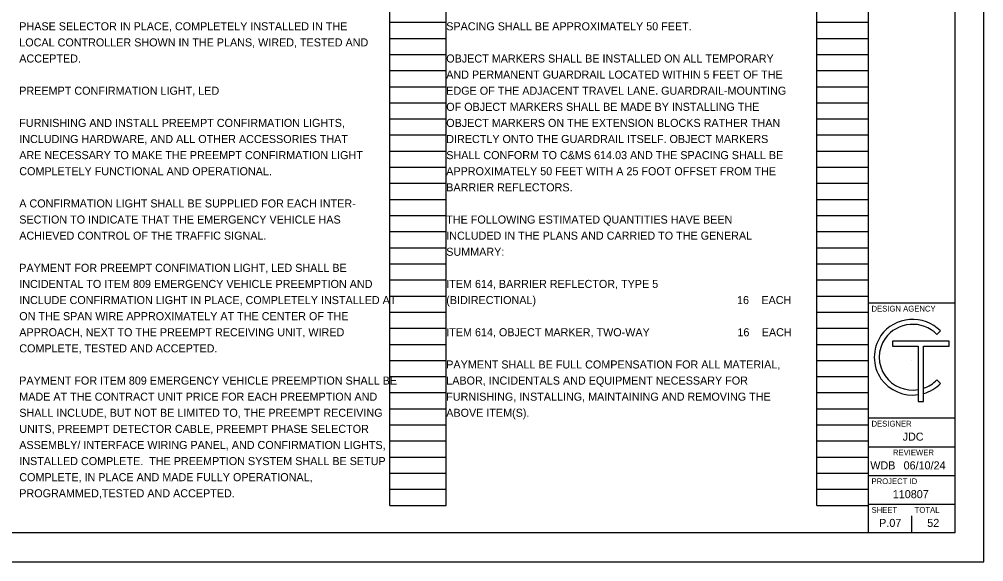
# Model space of a CAD drawing. Extents: x 0 to 34, y 0 to 22.
# Drawn here: x 17.24 to 34, y 0 to 9.43 of the extents above; entities that cross this region are included whole.
import ezdxf

# ---------------------------------------------------------------- set-up
doc = ezdxf.new("R2010")
doc.units = 0
for name, color, linetype in [('SH_Border', 7, 'Continuous'), ('SH_Cut_Line', 7, 'Continuous'), ('SH_Data', 7, 'Continuous'), ('SH_Text', 7, 'Continuous')]:
    doc.layers.add(name, color=color, linetype=linetype)

msp = doc.modelspace()

# ---------------------------------------------------------------- linework, layer by layer
at = {"layer": 'SH_Border'}
for p, q in [((32, 0.5), (32, 21.5)), ((32, 4.5), (33.5, 4.5)), ((32, 2.5), (33.5, 2.5)), ((32, 2), (33.5, 2)), ((32, 1.5), (33.5, 1.5)), ((32, 1), (33.5, 1))]:
    msp.add_line(p, q, dxfattribs=at)
msp.add_lwpolyline([(1.5, 21.5), (33.5, 21.5), (33.5, 0.5), (1.5, 0.5)], close=True, dxfattribs=at)
at = {"layer": 'SH_Cut_Line'}
msp.add_lwpolyline([(0, 0), (34, 0), (34, 22), (0, 22)], close=True, dxfattribs=at)
at = {"layer": 'SH_Data'}
for p, q in [((23.68, 0.98), (23.68, 21.14)), ((24.66, 0.98), (24.66, 21.14)), ((31.1, 0.98), (31.1, 21.14)), ((32, 0.98), (32, 21.14)), ((23.68, 9.38), (24.66, 9.38)), ((31.1, 9.38), (32, 9.38)), ((23.68, 9.1), (24.66, 9.1)), ((31.1, 9.1), (32, 9.1)), ((23.68, 8.82), (24.66, 8.82)), ((31.1, 8.82), (32, 8.82)), ((23.68, 8.54), (24.66, 8.54)), ((31.1, 8.54), (32, 8.54)), ((23.68, 8.26), (24.66, 8.26)), ((31.1, 8.26), (32, 8.26)), ((23.68, 7.98), (24.66, 7.98)), ((31.1, 7.98), (32, 7.98)), ((23.68, 7.7), (24.66, 7.7)), ((31.1, 7.7), (32, 7.7)), ((23.68, 7.42), (24.66, 7.42)), ((31.1, 7.42), (32, 7.42)), ((23.68, 7.14), (24.66, 7.14)), ((31.1, 7.14), (32, 7.14)), ((23.68, 6.86), (24.66, 6.86)), ((31.1, 6.86), (32, 6.86)), ((23.68, 6.58), (24.66, 6.58)), ((31.1, 6.58), (32, 6.58)), ((23.68, 6.3), (24.66, 6.3)), ((31.1, 6.3), (32, 6.3)), ((23.68, 6.02), (24.66, 6.02)), ((31.1, 6.02), (32, 6.02)), ((23.68, 5.74), (24.66, 5.74)), ((31.1, 5.74), (32, 5.74)), ((23.68, 5.46), (24.66, 5.46)), ((31.1, 5.46), (32, 5.46)), ((23.68, 5.18), (24.66, 5.18)), ((31.1, 5.18), (32, 5.18)), ((23.68, 4.9), (24.66, 4.9)), ((31.1, 4.9), (32, 4.9)), ((23.68, 4.62), (24.66, 4.62)), ((31.1, 4.62), (32, 4.62)), ((23.68, 4.34), (24.66, 4.34)), ((31.1, 4.34), (32, 4.34)), ((23.68, 4.06), (24.66, 4.06)), ((31.1, 4.06), (32, 4.06)), ((23.68, 3.78), (24.66, 3.78)), ((31.1, 3.78), (32, 3.78)), ((23.68, 3.5), (24.66, 3.5)), ((31.1, 3.5), (32, 3.5)), ((32.75, 3.5), (32.75, 3.5)), ((23.68, 3.22), (24.66, 3.22)), ((31.1, 3.22), (32, 3.22)), ((23.68, 2.94), (24.66, 2.94)), ((31.1, 2.94), (32, 2.94)), ((23.68, 2.66), (24.66, 2.66)), ((31.1, 2.66), (32, 2.66)), ((23.68, 2.38), (24.66, 2.38)), ((31.1, 2.38), (32, 2.38)), ((23.68, 2.1), (24.66, 2.1)), ((31.1, 2.1), (32, 2.1)), ((23.68, 1.82), (24.66, 1.82)), ((31.1, 1.82), (32, 1.82)), ((23.68, 1.54), (24.66, 1.54)), ((31.1, 1.54), (32, 1.54)), ((23.68, 1.26), (24.66, 1.26)), ((31.1, 1.26), (32, 1.26)), ((23.68, 0.98), (24.66, 0.98)), ((31.1, 0.98), (32, 0.98)), ((32.375, 0.675), (32.375, 0.675)), ((32.75, 0.5), (32.75, 0.8))]:
    msp.add_line(p, q, dxfattribs=at)
at = {"layer": 'SH_Text'}
for p, q in [((33.249, 4.013), (33.187, 3.952)), ((33.249, 4.013), (33.187, 3.952)), ((33.402, 3.833), (32.414, 3.833)), ((32.414, 3.833), (32.414, 3.751)), ((32.414, 3.751), (32.863, 3.751)), ((32.863, 3.751), (32.863, 2.785)), ((32.956, 2.785), (32.956, 3.751)), ((32.956, 3.751), (33.402, 3.751)), ((33.402, 3.751), (33.402, 3.833)), ((33.187, 3.16), (33.249, 3.099)), ((33.187, 3.16), (33.249, 3.099)), ((32.863, 2.993), (32.863, 2.905)), ((32.863, 2.993), (32.863, 2.905)), ((32.956, 2.925), (32.956, 3.016)), ((32.956, 2.925), (32.956, 3.016)), ((32.863, 2.785), (32.956, 2.785))]:
    msp.add_line(p, q, dxfattribs=at)
msp.add_lwpolyline([(32.863, 3.751), (32.863, 2.785), (32.956, 2.785), (32.956, 3.751), (33.402, 3.751), (33.402, 3.833), (32.414, 3.833), (32.414, 3.751)], close=True, dxfattribs=at)
for centre, radius, start, end in [((32.766, 3.535), 0.68, 44.7027, 144.3276), ((32.766, 3.535), 0.68, 44.7027, 144.3276), ((32.766, 3.535), 0.593, 44.7362, 144.1102), ((32.766, 3.535), 0.593, 44.7362, 144.1102), ((32.764, 3.556), 0.666, 145.7329, 214.2671), ((32.764, 3.556), 0.666, 145.7329, 214.2671), ((32.764, 3.556), 0.579, 145.7266, 214.2734), ((32.764, 3.556), 0.579, 145.7266, 214.2734), ((32.766, 3.578), 0.593, 215.8898, 279.4882), ((32.766, 3.578), 0.593, 215.8898, 279.4882), ((32.766, 3.578), 0.68, 215.6724, 278.2613), ((32.766, 3.578), 0.68, 215.6724, 278.2613), ((32.766, 3.578), 0.593, 288.6992, 315.2638), ((32.766, 3.578), 0.593, 288.6992, 315.2638), ((32.766, 3.578), 0.68, 286.2291, 315.2973), ((32.766, 3.578), 0.68, 286.2291, 315.2973)]:
    msp.add_arc(centre, radius, start, end, dxfattribs=at)

# ---------------------------------------------------------------- texts
at = {"layer": 'SH_Data'}
for s, height, p in [('DESIGN AGENCY', 0.1, (32.05, 4.35)), ('DESIGNER', 0.1, (32.05, 2.35)), ('JDC', 0.14, (32.591, 2.105)), ('REVIEWER', 0.1, (32.422, 1.85)), ('WDB', 0.14, (32.029, 1.605)), ('06/10/24', 0.14, (32.608, 1.605)), ('PROJECT ID', 0.1, (32.05, 1.35)), ('110807', 0.14, (32.42, 1.105)), ('SHEET', 0.1, (32.05, 0.85)), ('TOTAL', 0.1, (32.8, 0.85)), ('P.07', 0.14, (32.183, 0.605)), ('52', 0.14, (33.019, 0.605))]:
    msp.add_text(s, height=height, dxfattribs=at).set_placement(p)
at = {"layer": 'SH_Text'}
for s, p in [('PHASE SELECTOR IN PLACE, COMPLETELY INSTALLED IN THE ', (17.24, 9.24)), ('SPACING SHALL BE APPROXIMATELY 50 FEET.', (24.66, 9.24)), ('LOCAL CONTROLLER SHOWN IN THE PLANS, WIRED, TESTED AND', (17.24, 8.96)), ('ACCEPTED.', (17.24, 8.68)), ('OBJECT MARKERS SHALL BE INSTALLED ON ALL TEMPORARY', (24.66, 8.68)), ('AND PERMANENT GUARDRAIL LOCATED WITHIN 5 FEET OF THE', (24.66, 8.4)), ('PREEMPT CONFIRMATION LIGHT, LED', (17.24, 8.12)), ('EDGE OF THE ADJACENT TRAVEL LANE. GUARDRAIL-MOUNTING', (24.66, 8.12)), ('OF OBJECT MARKERS SHALL BE MADE BY INSTALLING THE', (24.66, 7.84)), ('FURNISHING AND INSTALL PREEMPT CONFIRMATION LIGHTS,', (17.24, 7.56)), ('OBJECT MARKERS ON THE EXTENSION BLOCKS RATHER THAN', (24.66, 7.56)), ('INCLUDING HARDWARE, AND ALL OTHER ACCESSORIES THAT ', (17.24, 7.28)), ('DIRECTLY ONTO THE GUARDRAIL ITSELF. OBJECT MARKERS', (24.66, 7.28)), ('ARE NECESSARY TO MAKE THE PREEMPT CONFIRMATION LIGHT ', (17.24, 7)), ('SHALL CONFORM TO C&MS 614.03 AND THE SPACING SHALL BE', (24.66, 7)), ('COMPLETELY FUNCTIONAL AND OPERATIONAL.', (17.24, 6.72)), ('APPROXIMATELY 50 FEET WITH A 25 FOOT OFFSET FROM THE', (24.66, 6.72)), ('BARRIER REFLECTORS.', (24.66, 6.44)), ('A CONFIRMATION LIGHT SHALL BE SUPPLIED FOR EACH INTER-', (17.24, 6.16)), ('SECTION TO INDICATE THAT THE EMERGENCY VEHICLE HAS', (17.24, 5.88)), ('THE FOLLOWING ESTIMATED QUANTITIES HAVE BEEN', (24.66, 5.88)), ('ACHIEVED CONTROL OF THE TRAFFIC SIGNAL.', (17.24, 5.6)), ('INCLUDED IN THE PLANS AND CARRIED TO THE GENERAL', (24.66, 5.6)), ('SUMMARY:', (24.66, 5.32)), ('PAYMENT FOR PREEMPT CONFIMATION LIGHT, LED SHALL BE ', (17.24, 5.04)), ('INCIDENTAL TO ITEM 809 EMERGENCY VEHICLE PREEMPTION AND ', (17.24, 4.76)), ('ITEM 614, BARRIER REFLECTOR, TYPE 5 ', (24.66, 4.76)), ('INCLUDE CONFIRMATION LIGHT IN PLACE, COMPLETELY INSTALLED AT ', (17.24, 4.48)), ('(BIDIRECTIONAL)                                                                     ', (24.66, 4.48)), ('  16  ', (29.609, 4.48)), ('  EACH', (30.032, 4.48)), ('ON THE SPAN WIRE APPROXIMATELY AT THE CENTER OF THE ', (17.24, 4.2)), ('APPROACH, NEXT TO THE PREEMPT RECEIVING UNIT, WIRED ', (17.24, 3.92)), ('ITEM 614, OBJECT MARKER, TWO-WAY                              ', (24.66, 3.92)), ('  16  ', (29.616, 3.92)), ('  EACH', (30.039, 3.92)), ('COMPLETE, TESTED AND ACCEPTED.', (17.24, 3.64)), ('PAYMENT SHALL BE FULL COMPENSATION FOR ALL MATERIAL,', (24.66, 3.36)), ('PAYMENT FOR ITEM 809 EMERGENCY VEHICLE PREEMPTION SHALL BE ', (17.24, 3.08)), ('LABOR, INCIDENTALS AND EQUIPMENT NECESSARY FOR', (24.66, 3.08)), ('MADE AT THE CONTRACT UNIT PRICE FOR EACH PREEMPTION AND ', (17.24, 2.8)), ('FURNISHING, INSTALLING, MAINTAINING AND REMOVING THE', (24.66, 2.8)), ('SHALL INCLUDE, BUT NOT BE LIMITED TO, THE PREEMPT RECEIVING ', (17.24, 2.52)), ('ABOVE ITEM(S).', (24.66, 2.52)), ('UNITS, PREEMPT DETECTOR CABLE, PREEMPT PHASE SELECTOR ', (17.24, 2.24)), ('ASSEMBLY/ INTERFACE WIRING PANEL, AND CONFIRMATION LIGHTS, ', (17.24, 1.96)), ('INSTALLED COMPLETE.  THE PREEMPTION SYSTEM SHALL BE SETUP ', (17.24, 1.68)), ('COMPLETE, IN PLACE AND MADE FULLY OPERATIONAL, ', (17.24, 1.4)), ('PROGRAMMED,TESTED AND ACCEPTED.', (17.24, 1.12))]:
    msp.add_text(s, height=0.14, dxfattribs=at).set_placement(p)

doc.saveas('drawing.dxf')
